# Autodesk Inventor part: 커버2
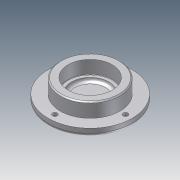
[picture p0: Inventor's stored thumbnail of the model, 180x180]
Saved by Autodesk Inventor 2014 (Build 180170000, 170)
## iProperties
Company: 한국ATC센터
Created: 2014-10
Part Number: 커버2
Document SubType Name: Modeling
Designer: KYOUNG IL JANG
Density: 1 g/cm^3
Mass: 44.7286 g
Surface Area: 161.165 cm^2
Volume: 44.7286 cm^3
Material: 일반
Appearance: 기본값
Author: KYOUNG IL JANG
Revision Number: 1
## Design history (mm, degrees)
sketch "스케치1"
  geometry: C1 r 38 at (0, 0); 1 further point
  constraints: 1 centre point, 1 coincident
  dimensions: "d0" = 76 diameter of C1
extrude "돌출1" new body sketch "스케치1" distance "d1" = 7; taper "d2" = 0 deg
sketch "스케치2"
  geometry: C1 r 27 at (0, 0); 1 further point
  constraints: 1 centre point, 1 coincident
  dimensions: "d3" = 54 diameter of C1
extrude "돌출2" join sketch "스케치2" distance "d4" = 13; taper "d5" = 0 deg
hole "구멍2" diameter "d20" = 34; stored, may be unused: countersink angle "d24" = 90 deg, drill point angle "d26" = 0 deg; dims "d18" = 10, "d19" = 10, "d21" = 6, "d22" = 40, "d23" = 12, "d25" = 3
fillet "모깎기2" dims "d34" = 3
fillet "모깎기1" dims "d27" = 0.3
chamfer "모따기1" distance "d28" = 1; stored, may be unused: second distance "d29" = 2, angle "d30" = 45 deg
sketch "스케치4" dims "d35" = 64
  geometry: 3 further points
  constraints: 2 horizontal alignment, 1 coincident, 2 other
hole "구멍3" sketch "스케치4" at (32, 0) diameter "d36" = 4.5; stored, may be unused: countersink angle "d40" = 90 deg, drill point angle "d42" = 118 deg; dims "d37" = 6, "d38" = 8, "d39" = 4.4, "d41" = 13
node "솔리드1"
pattern_circular "원형 패턴1" dims angle "d44" = 360 deg
